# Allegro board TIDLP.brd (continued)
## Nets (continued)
SWNODE_CORE: D502.1 L5.1 Q2.3 U15.25
SWNODE_MOT: D6.1 L6.2 U15.10
SWNODE_MOT2: D3.1 L2.2 U2.10
SWNODE_P2P5V: D7.1 L8.1 U15.41
SWNODE_P3P3V: D8.1 L7.1 U15.43
SWNODE_P5V: D4.1 L4.2 U15.23
TCK: J28.9 J32.15 J47.5 R725.1 U11.N24
TDI: J28.5 J32.19 J47.2 R728.1 U11.N25
TDO1: J47.4 U11.N23
TDO2: J28.13 J32.11 R723.1 U11.N22
TILT_X: R528.2 U3.5
TILT_Y: R529.2 U3.2
TMS1: J47.3 U11.P25
TMS2: J28.7 J32.17 R727.1 U11.P26
TRACECLK: J32.6 RN507.12(B)
TRACECLKR: RN507.5(A) U11.D7
TRACEPKT0: J32.30 J33.1 R659.2 RN508.9(B)
TRACEPKT0R: RN508.8(A) U11.C2
TRACEPKT1: J32.28 J33.2 R658.2 RN508.10(B)
TRACEPKT1R: RN508.7(A) U11.D3
TRACEPKT2: J32.26 J33.3 R657.2 RN508.11(B)
TRACEPKT2R: RN508.6(A) U11.E6
TRACEPKT3: J32.24 J33.4 R656.2 RN508.12(B)
TRACEPKT3R: RN508.5(A) U11.D5
TRACEPKT4: J32.22 J33.5 R655.2 RN508.13(B)
TRACEPKT4R: RN508.4(A) U11.E7
TRACEPKT5: J32.20 J33.6 RN508.14(B)
TRACEPKT5R: RN508.3(A) U11.C4
TRACEPKT6: J32.18 J33.7 RN508.15(B)
TRACEPKT6R: RN508.2(A) U11.B4
TRACEPKT7: J32.16 J33.8 RN508.16(B)
TRACEPKT7R: RN508.1(A) U11.E8
TRACESYNC: J32.32 RN507.13(B)
TRACESYNCR: RN507.4(A) U11.A5
TRSTZ: J32.21 J47.1 R733.1 U11.M23 U516.4
TRSTZ_IN: J28.3 R729.1 R734.2 U516.1
UART0_CTSZ: U6.12 U9.2
UART0_CTSZ_BUF: U9.6 U11.AE2
UART0_CTSZ_CON: J10.7 U6.13
UART0_DCD_CON: J10.1 R12.1
UART0_DSR_CON: J10.6 R12.2 R13.2
UART0_DTR_CON: J10.4 R13.1
UART0_RSTZ_CON: J10.8 U6.14
UART0_RTSZ: U10.5 U11.AD2
UART0_RTSZ_BUF: R542.2 R617.1 U6.11 U10.3
UART0_RXD: R613.1 U6.9 U9.5
UART0_RXD_BUF: U9.3 U11.AD1
UART0_RXD_CON: J10.3 U6.8
UART0_TXD: U10.2 U11.AB3
UART0_TXD_BUF: R543.1 U6.10 U10.6
UART0_TXD_CON: J10.2 U6.7
UART1_CTSZ: U11.E18 U12.12
UART1_CTSZ_CON: J21.7 U12.13
UART1_DCD_CON: J21.1 R21.1
UART1_DSR_CON: J21.6 R21.2 R22.2
UART1_DTR_CON: J21.4 R22.1
UART1_RSTZ_CON: J21.8 U12.14
UART1_RTSZ: U11.A19 U12.11
UART1_RXD: J3.92 U11.D19 U12.9
UART1_RXD_CON: J21.3 U12.8
UART1_TXD: J3.53 U11.C19 U12.10
UART1_TXD_CON: J21.2 U12.7
USB_DAT_N: J5.2 R515.1 U503.4
USB_DAT_NS: DN504.1(TP-1) R515.2 U11.C5
USB_DAT_P: J5.3 R516.1 R539.1 U503.6
USB_DAT_PS: DN504.2(TP-2) R516.2 U11.D6
USB_ENZ: R538.1 U11.E25 U504.1
XCLKIN: R536.1 U7.90
XCLKOUT: TP19.1 U7.66
XTAL_IN: C553.1 R580.1 U11.M26 X500.1
XTAL_OUT: R580.2 R581.2 U11.N26
N16773791: J3.1 R1.2
N16781966: J2.92 R8.2 R9.2
N16826457: Q4.3 R715.2
N16826574: Q3.3 Q4.2 R706.2
N16826732: Q503.3 R726.1
N16826745: Q3.2 R707.2
N16826772: J22.1 R630.2
N16826808: C32.2 Q5.1 R37.1 R726.2
N16827011: C554.1 R581.1 X500.2
N16827097: Q503.2 R599.2
N16827292: R668.1 U15.1
N16827323: R38.2 R52.1 U17.4
N16827429: D9.2 R714.2
N16827460: R39.2 U17.1
N16827499: D9.3 R716.2
N16827743: D10.2 R40.2
N16827874: D9.4 R715.1
N16830133: R684.1 R685.1 U512.1 U512.3 U512.11
N16830205: C667.1 R678.1 R679.2 U15.30 U512.4
N16830232: Q2.2 Q2.4 R634.1 U15.28
N16830236: D5.2 L5.2
N16830344: C675.2 C676.2 Q505.3 R677.2 R680.2 R717.2
N16830356: R639.1 U510.6
N16830372: D5.1 R25.1
N16830397: R640.2 U510.5
N16830529: R637.1 R638.1 U510.1 U510.2 U510.3
N16830564: R682.1 U512.6
N16830576: C675.1 R670.2 R677.1 U15.32 U512.14
N16830606: Q505.1 U15.33
N16830689: R680.1 U512.12
N16830707: R681.2 U512.13
N16830891: R683.2 U512.5
N16836092: C702.2 J64.1 L506.1 R761.1 R779.2
N16836211: R763.2 TP70.1 U521.3 VR2.2
N16862598: J53.3 R785.2 R786.2
N16862628: Q504.2 R687.1
N16862652: R643.2 U511.4
N16862691: R787.2 U526.4
N16862716: C709.2 R774.2 R775.2 U526.5
N16862889: C644.2 R641.2 R642.2 U511.5
N16862891: Q504.3 R686.2
N16869658: J6.1 R530.2 U4.1
N16869662: R548.2 U4.55 U4.56
N16888382: J52.1 J52.8 R753.1
N16888389: J52.13 R737.1
N16888395: J52.11 R739.1
N16888418: J52.12 R738.1
N16902445: J9.5 R626.1 R649.1
N16906032: C21.1 U12.2
N16906053: C20.1 U12.6
N16906057: C577.2 U12.1
N16906061: C577.1 U12.3
N16906093: C576.2 U12.4
N16906098: C576.1 U12.5
N16906262: R540.1 R541.1 U6.16 U9.8 U10.8
N16906499: C8.1 U6.2
N16906505: J5.1 R537.2 U504.2
N16906696: C7.1 U6.6
N16906819: C515.2 U6.1
N16906911: C515.1 U6.3
N16906913: R539.2 U504.4
N16907106: C507.2 U6.4
N16907207: C507.1 U6.5
N16910878: R610.2 U14.53
N16910921: R698.1 R699.2 U14.16
N16911179: R608.2 U14.29
N16911537: R696.2 U14.27
N16912987: R697.2 U14.17
N16969756: R66.2 R506.1 R507.1 R508.2
N16969826: R756.1 U500.1 U520.1
N16973926: C517.2 C518.2 R517.2 U5.5 U5.8
N16985744: R666.1 U2.1
N17028370: R45.1 U517.23
N17028379: R41.1 U517.22
N17028388: R46.1 U517.21
N17028397: R42.1 U517.20
N17028406: R47.1 U517.19
N17028415: R43.1 U517.18
N17028424: R44.1 U517.17
N17028433: R55.1 U517.16
N17028442: R54.1 U517.15
N17028451: R56.1 U517.11
N17031378: C701.2 J65.1 L505.1 R760.1 R778.2
N17031778: C700.2 J66.1 L504.1 R759.1 R777.2
N17032456: C691.2 J42.1 L503.1 R732.1 R744.2
N17032580: C690.2 J43.1 L502.1 R731.1 R743.2
N17032754: C689.2 J44.1 L501.1 R730.1 R742.2
N17036356: R765.2 TP67.1 U521.5 VR1.2
N17038227: J57.2 R768.1
N17038557: J58.2 R782.1
N17038579: R782.2 U522.4
N17059521: R511.1 U501.1 U501.2 U501.3 U501.11
N17059557: C510.1 R523.1 R524.2 U2.30 U501.4
N17059579: Q1.2 Q1.4 R11.1 U2.28
N17059583: D500.2 L1.2
N17059602: D500.1 R525.1
N17059826: R510.2 U501.5
N17060167: R509.1 U501.6
N17126992: R623.2 U11.AC10
N17126998: R624.2 U11.AF10
N17133391: C565.1 FB504.1 J11.1
N17140999: C524.1 R565.2
N17141409: C514.1 FB500.1 U502.4
N17141519: R536.2 U502.3
N17172867: R625.2 U11.AD10
N17173381: C677.2 R709.1 R720.2 TP46.1 U515.3
N17173524: C678.2 R708.1 R709.2
N17223452: C16.1 C521.1 FB4.1 FB5.1 FB6.1 FB7.1 R526.2
N17234365: C15.1 C522.1 FB1.1 FB2.1 FB3.1 R527.2
N17320383: TP25.1 U7.27
N17320387: TP24.1 U7.28
N17320392: TP26.1 U7.29
N17373497: R513.1 R575.1 R588.1
N17385870: R622.2 U11.AB11
N17410797: C529.2 Q500.3 R522.2 R576.2
N17410821: Q500.1 U2.33
N17410829: R521.2 R522.1 U2.32
N17418050: R749.1 U518.12
N17418052: R750.1 U518.9
N17418070: R746.1 U518.7
N17418072: R748.1 U518.4
N17418086: J46.3 U519.22 U525.2
N17418489: J48.1 R747.1 U518.1
N17423586: J46.1 R751.1 U525.4
N17451899: R710.2 SW1.1
N17529082: Q507.2 R776.2
N17529223: Q506.1 Q507.3 R758.1
N17529899: C699.2 J67.1 Q506.3
N17530429: C540.1 Q502.2 R16.1
N17530493: Q501.2 Q502.3 R15.1
N17530807: Q501.3 R573.1
N17554994: R518.1 U501.12
N17554995: R513.2 U501.13
N173644741: C542.2 R574.1

Pads without a net: J5 S1 S2; J9 7 8; J11 6 7; J22 6 7; J29 5 6; J41 5 6; J47 7 8; J49 7 8; J52 15 16; J53 7 8; J54 5 6; J55 5 6; J56 5 6; MT1 2 3 4 5 6 7 8 9; MT2 2 3 4 5 6 7 8 9; MT3 2 3 4 5 6 7 8 9; MT4 2 3 4 5 6 7 8 9; MT5 2 3 4 5 6 7 8 9; MT6 2 3 4 5 6 7 8 9; NOREF#3 1; NOREF#13 1; NOREF#14 1; NOREF#19 1; NOREF#20 1; NOREF#21 1; U20 PAD; U515 5 6 7

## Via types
v1: diameter 0.61, hole 0.305, TOP to BOTTOM, 2108 vias
v2: diameter 0.483, hole 0.229, TOP to BOTTOM, 581 vias

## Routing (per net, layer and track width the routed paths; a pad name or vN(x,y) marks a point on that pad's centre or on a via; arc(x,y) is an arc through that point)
AGND: length 45.6
  TOP w0.203: U7.25 32.88,90.05 33.09,89.83 v1(33.54,89.83)
  TOP w0.254: v1(40.77,91.5) 41.14,91.13 U7.39 ; 34.16,96.02 U7.14 ; 34.16,96.02 34.04,96.14 34.04,96.33 33.85,96.52 U7.13 ; 34.16,96.02 34.42,95.76 34.42,95 v1(34.54,94.87)
  TOP w0.508: J11.2 v1(15.07,95.91) ; v1(20.84,98.25) 20.84,98.76 19.94,99.66 J11.5 15.85,99.66 v1(15.43,100.08)
  BOTTOM w0.254: v1(39.05,90.17) 40.07,89.15 C573.2
  BOTTOM w0.508: R571.2 v1(20.84,98.25) ; C559.2 C560.2 34.37,90.67 v1(33.54,89.83) ; C558.2 34.62,94.79 v1(34.54,94.87) ; C561.2 33.92,95.49 v1(34.54,94.87) ; C574.2 v1(33.34,88.01) ; v1(15.43,100.08) 15.46,100.05 C539.2 R572.2 ; C564.2 20.25,96.22 v1(21.78,97.74) ; C565.2 16.83,95.91 v1(15.07,95.91) ; v1(24.58,94.87) 25.83,94.87 C563.2 ; C575.2 v1(33.46,85.98) ; v1(34.54,94.87) 33.13,93.46 C562.2 ; R583.2 40.83,90.22 40.83,90.11 40.25,89.52 C573.2 40.58,88.82 40.58,88.71 40.64,88.65 R598.2 ; v1(30.61,94.89) 31,95.28 R585.2 ; R586.1 v1(27.11,90.93)
GND: length 1203.6
  TOP w0.178: U11.R5 v2(95.66,67.2) ; U11.F18 v2(85.66,81.2) ; U11.AE17 v2(105.66,80.2) ; U11.B2 v2(81.66,64.2) ; U11.M25 v2(91.66,88.2) ; U11.C3 v2(82.66,65.2) ; U11.F15 v2(85.66,78.2) ; U11.AC6 v2(103.66,68.2) ; U11.A3 v2(80.66,65.2) ; U11.D18 v2(83.66,81.2) ; U11.AC4 v2(103.66,66.2) ; U11.A1 v2(80.66,63.2) ; U11.AB17 v2(102.66,80.2) ; U11.D17 v2(83.66,80.2) ; U11.AB5 v2(102.66,67.2) ; U11.J6 v2(88.66,68.2) ; U11.F21 v2(85.66,84.2) ; U11.AF1 v2(106.66,63.2) ; U11.F6 86.14,68.7 v2(85.66,68.23) ; U11.AD3 v2(104.66,65.2) ; U11.L23 v2(90.66,86.2) ; U11.AF17 v2(106.66,80.2) ; U11.B3 v2(81.66,65.2) ; U11.F9 v2(85.66,71.2) ; U11.R24 v2(95.66,87.2) ; U11.M21 v2(91.66,84.2) ; U11.M22 v2(91.66,85.2) ; U11.AD18 v2(104.66,81.2) ; U11.L25 v2(90.66,88.2) ; U11.P24 v2(94.66,87.2) ; U11.K5 v2(89.66,67.2) ; U11.E15 v2(84.66,78.2) ; U11.G5 v2(86.66,67.2) ; U11.C18 v2(82.66,81.2) ; U11.F12 v2(85.66,74.2) ; U11.A2 v2(80.66,64.2) ; U11.J5 v2(88.66,67.2) ; U11.A24 v2(80.66,87.2) ; U11.B18 v2(81.66,81.2) ; U11.K26 v2(89.66,89.2) ; U11.L5 v2(90.66,67.2) ; U11.V6 v2(98.66,68.2) ; U11.B1 v2(81.66,63.2) ; U11.E17 v2(84.66,80.2) ; U11.AF3 v2(106.66,65.2) ; U11.AE3 v2(105.66,65.2) ; U11.AC17 v2(103.66,80.2) ; U11.AB15 v2(102.66,78.2) ; U11.Y5 v2(100.66,67.2) ; U11.A18 v2(80.66,81.2) ; U11.AA9 v2(101.66,71.2) ; U11.A25 v2(80.66,88.2) ; U11.E16 v2(84.66,79.2) ; U11.B25 v2(81.66,88.2) ; U11.AA12 v2(101.66,74.2) ; U11.E5 v2(84.66,67.2) ; U11.C24 v2(82.66,87.2) ; U11.AB16 v2(102.66,79.2) ; U11.M6 v2(91.66,68.2) ; U11.E22 v2(84.66,85.2) ; U11.D4 v2(83.66,66.2) ; U11.AA6 v2(101.66,68.2) ; U11.W5 v2(99.66,67.2) ; U11.AF2 v2(106.66,64.2) ; U11.U5 v2(97.66,67.2) ; U11.AB14 v2(102.66,77.2) ; U11.AC18 v2(103.66,81.2) ; U11.J21 v2(88.66,84.2) ; U11.R6 v2(95.66,68.2) ; U11.A17 v2(80.66,80.2) ; U11.D23 v2(83.66,86.2) ; U11.B17 v2(81.66,80.2) ; U11.V5 v2(98.66,67.2) ; U11.AD17 v2(104.66,80.2) ; U11.R26 v2(95.66,89.2) ; U11.A26 v2(80.66,89.2) ; U11.N5 v2(92.66,67.2)
  TOP w0.203: U7.69 46.82,99.52 v1(46.72,99.62) ; v1(48.28,57.1) 48.5,57.32 U14.1 ; U7.49 46.14,89.6 v1(45.66,90.08)
  TOP w0.254: U14.33 60,79.64 v1(59.71,79.92) ; U11.AB22 v2(102.66,85.2) ; U8.13 63.92,85.69 63.92,85.68 v1(63.92,85.63) ; U7.62 47.17,96.02 47.07,96.13 v1(47.07,96.26) ; v1(50.17,80.1) 50.49,79.78 U14.52 ; U11.R13 v2(95.66,75.2) ; U11.N15 v2(92.66,78.2) ; v1(183.9,10.46) 184.17,10.74 U20.19 ; U7.89 40.14,102.94 ; 40.14,102.94 40.26,103.06 40.45,103.06 40.64,103.25 U7.88 ; 40.14,102.94 v1(39.94,102.74) ; v1(38.42,84.45) 39.14,85.18 U7.35 ; U15.7 162.18,61.08 v1(161.8,61.47) ; v2(98.66,84.2) U11.V21 ; v1(197.96,14.56) 197.87,14.47 194.21,14.47 J52.9 ; U4.49 78.56,102.37 v1(78.17,101.98) ; U2.19 160.91,115.83 v1(160.53,115.44) ; U11.R14 v2(95.66,77.2) ; U11.M16 v2(91.66,79.2) ; v1(90.17,1.97) 89.65,2.49 J59.5 ; U11.L12 v2(90.66,74.2) ; U11.R15 v2(95.66,78.2) ; v1(46.21,102.56) 46.14,102.63 U7.77 ; U11.P14 v2(94.66,77.2) ; U11.P15 v2(94.66,78.2) ; U11.R11 v2(95.66,73.2) ; U11.P13 v2(94.66,75.2) ; U2.44 161.91,109.97 162.29,110.34 162.29,111.15 v1(161.8,111.63) ; U11.T13 v2(96.66,75.2) ; U11.M13 v2(91.66,75.2) ; v1(59.35,85.89) 59.23,86.01 59.23,86.06 58.69,86.6 U8.12 ; U8.1 57.21,93.74 v1(56.63,94.33) ; U11.N14 v2(92.66,77.2) ; U11.N11 v2(92.66,73.2) ; U11.M14 v2(91.66,77.2) ; U11.AA15 v2(101.66,78.2) ; U2.7 163.45,113.79 v1(163.07,114.17) ; J52.10 196.8,13.94 197.16,13.58 v1(197.16,13.42) ; 159.64,63.25 159.64,63.25 159.64,63.56 159.69,63.61 159.69,64.13 159.64,64.18 U15.19 ; U7.41 42.14,87.48 v1(41.85,87.19) ; U4.8 78.56,108.93 78.18,108.55 78.18,107.62 v1(78.09,107.53) ; U11.P11 v2(94.66,73.2) ; v1(37.34,102.11) 37.34,103.12 37.64,103.43 U7.94 ; J59.11 86.65,2.32 ; U7.2 v1(31.39,102.02) ; U11.N13 v2(92.66,75.2) ; v1(47.08,93.53) 47.16,93.53 47.16,93.49 47.05,93.38 47.08,93.02 47.08,92.8 47.36,92.52 U7.55 ; U14.56 47.86,78.27 47.63,78.5 v1(47.63,78.46) ; U11.N12 v2(92.66,74.2) ; U11.AD24 v2(104.66,87.2) ; U4.19 73.06,111.68 73.04,111.93 72.99,111.97 72.99,112.03 72.99,112.28 v1(72.86,112.4) ; U11.L14 v2(90.66,77.2) ; U7.11 31.73,97.52 v1(31.37,97.16) ; v1(196.04,10.56) 196.16,10.68 196.16,11.28 195.51,11.94 J52.14 ; U11.M12 v2(91.66,74.2) ; U11.AA21 v2(101.66,84.2) ; J59.9 v1(87.65,4.47) ; J59.3 v1(90.65,4.48) ; U11.T15 v2(96.66,78.2) ; J59.7 v1(88.65,2.03) ; U11.AE25 v2(105.66,88.2) ; U11.AF26 v2(106.66,89.2) ; U11.N16 v2(92.66,79.2) ; v1(72.26,100.72) 72.76,101.22 72.76,101.49 72.82,101.56 72.82,102.27 72.83,102.28 72.83,102.37 72.85,102.38 72.85,102.38 73.04,102.58 73.04,102.58 73.06,102.6 U4.38 ; U11.T12 v2(96.66,74.2) ; U11.M15 v2(91.66,78.2) ; U11.P16 v2(94.66,79.2) ; U11.AA18 v2(101.66,81.2) ; U15.44 160.64,57.32 160.67,57.35 160.67,57.35 160.7,57.43 160.75,57.5 160.75,57.53 160.88,57.66 160.88,58.57 v1(160.53,58.93) ; U11.T14 v2(96.66,77.2) ; U11.AE24 v2(105.66,87.2) ; U11.R16 v2(95.66,79.2) ; U7.87 v1(41.14,102.69) ; U11.AC23 v2(103.66,86.2) ; U11.R12 v2(95.66,74.2) ; U11.L13 v2(90.66,75.2) ; U11.AF24 v2(106.66,87.2) ; U11.AF25 v2(106.66,88.2) ; U11.M11 v2(91.66,73.2) ; U11.L15 v2(90.66,78.2) ; U11.P12 v2(94.66,74.2)
  TOP w0.381: J42.3 v1(137.43,23.7) ; C19.2 v1(187.9,89.03) ; J31.3 v1(132.74,35.98) ; RN1.6 v1(42.46,80.54) ; J56.4 v1(52.1,4.67) ; v1(187.39,81.28) 187.85,81.74 C20.2 ; J39.5 v1(14.57,19.08) ; J60.3 v1(99.72,4.97) ; J30.3 119.54,37.67 119.18,37.32 v1(118.98,37.32) ; J57.3 63.77,3.38 v1(63.44,3.05) ; J33.10 v1(60.71,41.91) ; v1(172.66,22.42) 173.52,23.28 U16.4 ; U13.34 v1(33.45,67.55) ; D3.2 v1(167.04,103.91) ; D9.1 174.29,42.43 v1(174.22,42.5) ; U5.2 186.5,107.44 v1(187.26,106.68) ; U3.7 v1(178.12,113.79) ; J32.G5 48.26,39.37 J32.5 ; C29.1 v1(188.39,35.97) ; C17.1 v1(137.03,100.9) ; v1(73.47,3.17) 73.68,3.38 J58.3 ; v1(178.31,105.21) 178.55,104.97 C18.2 ; RN1.8 v1(44.18,80.5) 44.16,80.52 43.48,80.52 43.26,80.74 RN1.7 ; J38.1 2.9,14.08 2.67,13.84 2.67,13.08 v1(2.41,12.83) ; RN1.5 v1(41.55,79.72) ; R52.2 v1(180.85,28.26) ; U9.4 v1(128.85,85.93) ; C8.2 v1(191.13,116.14) ; U5.3 v1(184.86,110.1) ; R5.2 v1(168.47,119.32) ; U10.4 v1(133.24,85.93) ; J33.9 v1(57.53,39.37) ; U12.15 v1(191.74,68.54) ; v1(42.61,67.92) 43.03,68.34 U13.12 ; J54.4 v1(26.29,3.17) ; U3.3 v1(186.75,116.33) ; J10.5 v1(194.9,100.76) ; C7.2 v1(188.72,115.95) ; v1(178.57,25.96) 178.56,25.95 178.56,25.15 179.13,24.58 U16.7 ; U6.15 191.36,104.18 v1(191.83,104.65) ; J41.4 125.76,25.82 v1(125.79,25.85) ; v1(162.69,23.04) 162.76,23.11 163.7,23.11 163.85,23.26 J44.3 ; C21.2 v1(193.22,81.74) ; C28.1 184.25,35.97 v1(183.9,36.32) ; J24.1 v1(16.07,58.42) ; D10.1 v1(184.83,28.85) ; C37.1 v1(190.3,9.09) ; J55.4 v1(40.03,4.6) ; J47.6 v1(31.17,12.75) ; C33.1 v1(179.32,28.07) ; J33.11 v1(57.66,44.45) ; J49.6 v1(45.77,12.59) ; C1.1 166.12,124.08 166.75,123.44 v1(166.75,122.3) ; C26.1 v1(192.66,66.23) ; U19.2 v1(173.8,20.19) ; J22.5 v1(181.42,57.36) ; J24.20 v1(26.99,35.56) ; J33.12 v1(60.71,46.99) ; J67.3 174.01,2.2 v1(174.4,1.82) ; U18.3 v1(127.62,20.02) ; J21.5 v1(194.99,68.25) ; J53.2 v1(17.12,1.43)
  TOP w0.508: J5.4 7.83,104.47 v1(10.83,104.47) ; v1(88.44,109.1) 88.44,109.17 88.75,109.48 C14.2 ; Q4.1 175.14,46.23 v1(174.32,46.23) ; v1(152.92,47.76) 152.92,48.65 D8.2 ; D6.2 v1(169.56,51.21) ; v1(138.87,2.29) 138.87,2.33 139.72,3.17 J64.3 ; v1(73.91,116.97) 73.89,116.99 J2.G8 69.95,116.99 v1(69.91,117.03) 69.88,116.99 J2.G7 63.6,116.99 v1(63.56,117.03) 63.53,116.99 J2.G6 57.24,116.99 v1(57.21,116.97) 57.19,116.99 J2.G5 J2.G4 49.87,116.99 v1(49.85,116.97) 49.82,116.99 J2.G3 43.52,116.99 v1(43.5,116.97) 43.47,116.99 J2.G2 37.3,116.99 v1(37.27,116.97) 37.25,116.99 J2.G1 33.36,116.99 v1(33.34,116.97) ; v1(108.19,39.74) 107.98,39.53 J29.4 ; J43.3 150.87,23.7 v1(150.54,23.37) ; C13.2 87.48,109.12 v1(87.46,109.12) ; C23.1 v1(152.02,67.82) ; v1(163.97,73.78) 163.97,73.18 164.85,72.31 C22.1 ; D1.2 v1(135.47,112.5) ; C10.2 38.1,109.82 39.04,108.87 v1(40.01,108.87) ; VR1.1 v1(94.86,12.81) ; v1(84.38,116.6) 84.77,116.99 J3.G1 88.3,116.99 v1(88.33,116.97) 88.35,116.99 J3.G2 94.39,116.99 94.44,117.04 95.4,117.04 95.43,117.02 95.56,117.02 95.59,116.99 J3.G3 100.94,116.99 v1(100.97,116.97) 101.2,116.97 101.38,116.79 102.22,116.79 102.42,116.99 J3.G4 J3.G5 108.31,116.99 108.33,116.97 108.36,116.99 J3.G6 114.66,116.99 v1(114.68,116.97) 114.71,116.99 J3.G7 120.94,116.99 v1(120.97,116.97) 120.99,116.99 J3.G8 124.87,116.99 v1(125.01,117.13) ; v1(143.38,45.59) 142.65,46.33 D7.2 ; v1(85.92,1.91) 86.23,1.91 86.65,2.32 ; v1(162.5,2.16) 163.22,2.88 J66.3 ; C36.1 115.18,13.2 113.92,11.94 109.7,11.94 109.58,12.06 108.39,12.06 107.95,12.51 107.95,14.52 v1(108.27,14.83) 108.42,14.99 C35.1 ; C3.2 v1(38.73,124.52) ; R23.2 v1(166.69,69.67) ; J65.3 151.79,3.26 v1(150.81,2.29) ; D2.2 152.59,105.41 v1(151.01,106.99) ; v1(168.96,49.08) 169.92,49.08 Q3.1 ; J62.3 119.4,4.87 v1(119.13,5.15) ; v1(82.09,33.62) 81.94,33.77 C31.1 ; J35.3 v1(136.23,32.45) ; C9.2 v1(35.67,109.97) ; C11.2 v1(40.19,109.97) ; v1(94.62,34.98) 94.62,35.05 94.74,35.05 94.74,35.05 95.49,34.3 R34.2 ; C25.1 v1(167.06,66.56) ; C12.2 v1(86.21,109.13) ; C5.2 90.66,124.16 v1(91.03,124.52) 90.21,125.34 89.52,125.34 88.77,124.59 C4.2 ; C27.1 v1(135.57,48.56) ; v1(43.5,108.33) 42.48,107.31 J7.2 ; J9.6 v1(61.86,105.54) ; VR2.1 v1(122.14,15.39) ; C30.1 v1(78.35,34.81) ; C34.1 v1(26.37,26.99) ; C2.2 v1(37.47,124.52)
  LY2GND w0.508: TP44.1 163.52,54.36 162.79,53.63 ; TP44.1 164.34,53.21 164.37,53.17 ; TP44.1 166.55,54.36 166.81,54.1 ; TP44.1 164.34,55.51 164.55,55.72 ; J23.16 7.01,43.27 ; J23.16 5.5,43.27 ; J23.16 5.5,41.76 ; J23.16 7.01,41.76 ; J48.2 50.44,21.13 ; J48.2 48.81,19.51 ; J48.2 50.44,19.51 ; J48.2 48.81,21.13 ; 48.81,50.98 J25.2 ; J25.2 48.81,49.35 ; J25.2 50.44,50.98 ; J25.2 50.44,49.35 ; 83.86,14.78 J50.2 ; J50.2 85.49,14.78 ; J50.2 83.86,13.16 ; J50.2 85.49,13.16 ; 18.93,115.45 19.68,116.2 ; 19.68,116.2 18.93,116.96 ; 19.68,116.2 20.44,116.96 ; 19.68,116.2 20.44,115.45 ; J40.14 22.92,13.54 24.27,13.54 ; J40.14 22.86,12.46 22.82,12.42 ; J40.14 J40.13 ; J40.14 21.1,13.6 21.09,13.59 ; J28.16 35.1,45.26 ; J28.16 35.1,43.64 ; J28.16 33.48,45.26 ; J28.16 33.48,43.64 ; 66.18,97.71 J17.2 ; J17.2 67.81,97.71 ; J17.2 65.87,98.52 65.85,98.5 ; J17.2 66.99,98.88 66.23,99.64 ; J17.2 67.81,99.33 ; J17.2 66.18,99.33 ; J17.2 68.45,98.52 68.47,98.5 ; 185.27,5.23 186.06,4.45 ; 186.06,4.45 186.84,5.23 ; 186.06,4.45 186.84,3.66 ; 186.06,4.45 185.27,3.66 ; 48.17,40.73 J32.G5 ; J32.G5 49.62,39.28 ; J32.G5 48.17,39.28 ; J32.G5 49.62,40.73 ; J32.G1 49.62,30.57 ; J32.G1 49.62,29.12 ; J32.G1 48.17,29.12 ; J32.G1 48.17,30.57 ; U1.2 13.49,119.86 ; U1.2 11.91,119.86 ; U1.2 11.91,121.44 ; U1.2 13.49,121.44 ; J28.6 35.1,30.94 ; J28.6 33.48,32.56 ; J28.6 33.48,30.94 ; J28.6 35.1,32.56 ; 33.48,48.72 J28.20 ; J28.20 35.1,48.72 ; J28.20 35.1,50.34 ; J28.20 33.48,50.34 ; 8.26,42.52 9.01,43.27 ; 8.26,42.52 7.5,41.76 ; 8.26,42.52 7.5,43.27 ; 8.26,42.52 9.01,41.76 ; 18.93,110.37 19.68,111.12 ; 19.68,111.12 18.93,111.88 ; 19.68,111.12 20.44,110.37 ; 19.68,111.12 20.44,111.88 ; J6.2 38.06,108.13 ; J6.2 38.06,106.5 ; J6.2 36.43,108.13 ; J6.2 36.43,106.5 ; J23.10 7.01,47.76 ; J23.10 7.01,49.27 ; J23.10 5.5,49.27 ; J23.10 5.5,47.76 ; 6.56,74.91 J20.5 ; J20.5 6.56,73.19 ; J20.5 8.28,73.19 ; J20.5 8.28,74.91 ; J37.3 191.9,31.26 ; J37.3 190.37,31.26 ; J37.3 191.9,32.8 ; J37.3 190.37,32.8 ; J5.4 6.99,106.78 ; J5.4 5.52,106.78 ; J5.4 5.52,105.31 ; J5.4 6.99,105.31 ; 185.42,12.69 185.47,12.73 ; 185.42,12.69 U20.25 ; 185.42,12.69 185.35,12.61 ; J32.G2 49.62,33.11 ; J32.G2 48.17,33.11 ; J32.G2 48.17,31.66 ; J32.G2 49.62,31.66 ; 20.87,14.88 22.82,14.88 J40.13 ; 48.17,38.19 J32.G4 ; J32.G4 48.17,36.74 ; J32.G4 49.62,36.74 ; J32.G4 49.62,38.19 ; J37.1 191.9,25.27 ; J37.1 190.37,25.27 ; J37.1 190.37,26.8 ; J37.1 191.9,26.8 ; J40.13 22.9,14.81 24.24,14.81 ; 48.17,35.65 J32.G3 ; J32.G3 49.62,34.2 ; J32.G3 48.17,34.2 ; J32.G3 49.62,35.65 ; J37.5 194.9,25.27 ; J37.5 193.36,26.8 ; J37.5 194.9,26.8 ; J37.5 193.36,25.27 ; 7.5,49.76 J23.7 ; J23.7 9.01,49.76 ; J23.7 9.01,51.27 ; J23.7 7.5,51.27 ; J28.8 35.1,33.48 ; J28.8 33.48,35.1 ; J28.8 35.1,35.1 ; J28.8 33.48,33.48 ; 33.48,37.64 J28.10 ; J28.10 33.48,36.02 ; J28.10 35.1,36.02 ; J28.10 35.1,37.64 ; 19.68,118.75 20.44,117.99 ; 19.68,118.75 20.44,119.5 ; 19.68,118.75 18.93,119.5 ; 19.68,118.75 18.93,117.99 ; 190.89,3.51 190.9,3.5 MT6.1 196.5,9.15 196.33,9.32 ; 18.93,122.04 19.68,121.28 ; 19.68,121.28 20.44,122.04 ; 19.68,121.28 20.44,120.53 ; 19.68,121.28 18.93,120.53 ; J28.18 35.1,46.18 ; J28.18 35.1,47.8 ; J28.18 33.48,46.18 ; J28.18 33.48,47.8 ; U20.25 186.59,13.65 186.63,13.61 ; U20.25 185.42,14.67 185.46,14.71 ; U20.25 184.35,13.65 184.31,13.69 ; 188.25,127.58 188.34,127.5 MT3.1 196.5,122.45 196.1,122.05 ; 3.52,9.4 3.5,9.38 MT5.1 8.57,3.5 8.65,3.58 ; 193.36,31.26 J37.7 ; J37.7 194.9,32.8 ; J37.7 194.9,31.26 ; J37.7 193.36,32.8 ; 33.48,38.56 J28.12 ; J28.12 35.1,38.56 ; J28.12 35.1,40.18 ; J28.12 33.48,40.18 ; J28.4 35.1,30.02 ; J28.4 33.48,28.4 ; J28.4 35.1,28.4 ; J28.4 33.48,30.02 ; J28.14 35.1,41.1 ; J28.14 33.48,41.1 ; J28.14 35.1,42.72 ; J28.14 33.48,42.72
  LY2GND w1.27: 138.34,129.51 138.32,129.5 MT2.1 ; 3.45,125.04 3.45,120.05 MT4.1 ; MT2.1 127.57,129.5 127.45,129.37 ; MT2.1 132.63,124.76 132.5,124.64 ; MT1.1 25.63,124.27 25.48,124.12 ; MT1.1 25.59,129.53 19.63,129.53 ; MT1.1 30.94,129.5 31.07,129.63 ; MT4.1 3.35,119.85 3.35,115.77 ; MT4.1 3.51,120.01 8.06,120.01
  BOTTOM w0.102: C548.2 86.69,90.81 86.66,90.83 ; C549.2 96.32,90.42 95.66,89.76 v2(95.66,89.2) ; C602.2 88.76,81.41 ; C550.2 84.4,90.83 ; v2(90.66,86.2) 91.06,85.8 93.4,85.8 C546.2 ; v2(89.48,72.05) 89.57,72.05 89.53,72.01 v2(89.53,70.99) ; C645.2 93.83,88.69 92.15,88.69 v2(91.66,88.2) ; v2(89.66,89.2) 88.95,89.91 C547.2
  BOTTOM w0.254: v1(160.53,62.74) 160.22,63.04 C640.2 ; U512.2 139.59,56.1 139.84,55.86 139.84,55.08 139.39,54.63 138.5,54.63 138.41,54.74 v1(138.05,54.74) ; v2(91.66,73.2) 91.64,73.18 C625.2 ; v2(92.62,81.38) 92.67,81.43 C596.2 ; v1(176.21,116.2) 175.59,115.59 U501.10 ; v2(95.66,73.2) 95.68,73.18 C620.2 ; v1(163.07,114.17) 163.4,113.84 C512.1 ; C632.2 87.74,69.22 C628.2 88.6,70.05 v2(89.53,70.99) ; U512.10 142.76,58.05 142.03,58.78 142.03,59.76 141.35,60.44 140.4,60.44 139.95,59.99 v1(139.66,59.99) ; v1(90.65,4.48) 90.54,4.37 C705.1 ; v2(88.39,71.31) 88.33,71.25 C630.2 C631.2 ; U517.1 v1(31.73,27.6) ; U510.11 142.04,62.99 v1(141.44,62.38) ; v1(161.8,61.47) 162.13,61.14 C639.1 ; v1(177.26,112.82) 176.89,113.18 U501.8 ; v2(93.66,82.02) 93.79,82.14 C569.2 ; v2(90.81,70.99) C626.2 90.74,69.99 C627.2 ; U507.3 23.7,76.39 ; C595.2 95.19,82.35 94.93,82.09 94.93,81.66 v2(94.81,81.53) ; C594.2 96.11,82.26 96.11,81.95 95.69,81.53 v2(95.72,81.53) ; C568.2 99.87,82.61 C586.2 99.81,81.6 C590.2 99.69,81.53 v2(99.06,80.9) ; U517.12 v1(31.73,18.11) ; v1(145.45,60.33) 144.91,60.33 144.08,59.5 U512.8 ; C629.2 87.99,73.41 88.11,73.29 88.55,73.29 88.61,73.34 v2(89.09,73.34) ; U510.8 144.61,64.94 144.88,65.22 145.87,65.22 146.01,65.07 v1(146.01,65.06) ; v2(91.17,81.38) 91,81.56 C597.2 ; C622.2 94.61,70.93 v2(94.6,70.94) ; v2(88.81,81.36) 87.74,82.42 C601.2 C570.2 ; C606.1 54.99,75.69 54.94,75.64 54.94,75.68 54.91,75.68 54.91,75.68 54.91,75.68 54.91,75.68 54.91,75.68 v1(54.9,75.68) ; v2(88.68,80.09) 88.73,80.14 C598.2 ; v1(142.3,63.64) 142.31,63.64 142.31,63.64 U510.10 ; C588.2 v2(98.68,78.74) ; C624.2 v2(92.39,70.99) ; C600.2 89.79,82.28 C599.2 89.85,81.41 v2(89.9,81.36) ; C618.2 98.11,70.92 v2(98.13,70.94) ; C619.2 v2(96.71,70.92) ; v2(98.11,81.22) 98.74,81.85 C591.2 ; v2(88.39,72.52) 88.27,72.39 C633.2 ; R755.2 v1(188.34,11.43) ; U517.13 24.82,18.9 v1(24.25,19.47) ; U509.3 v1(24.13,71.63)
  BOTTOM w0.381: RN501.5 42.02,99.02 41.82,99.21 41.82,99.92 v1(41.83,99.93) RN501.6 ; U506.5 28.74,84.8 v1(29.03,85.09) 28.68,85.45 U506.4 ; C611.2 113.78,70.1 113.95,69.93 v1(114.64,69.93) ; C543.2 v1(179.39,92.08) ; C706.1 v1(63.44,3.05) ; C536.2 31.75,102.37 v1(31.39,102.02) ; R769.1 v1(59.82,8.51) ; DN501.1 v1(168.17,130.33) ; v2(98.87,72.39) 99.62,72.39 C615.2 ; R757.2 183.51,12.18 183.88,11.81 183.88,11.81 C693.1 184.26,10.77 183.9,10.4 v1(183.9,10.46) ; U506.1 v1(29.65,87.39) ; C659.2 95,66.54 v2(95.66,67.2) ; U521.4 108.19,6.14 108.1,6.05 v1(108.1,6.14) ; C682.1 v1(139.76,37.59) ; R574.2 174.24,95 v1(173.93,94.68) ; v1(178.63,106.49) 178.88,106.24 179.77,106.24 180.26,105.74 C518.1 ; v2(101.66,68.2) 101.66,68.4 C614.2 ; v1(46.21,102.56) 45.35,103.42 C531.2 ; R734.1 37.66,25.08 37.66,25.14 v1(37.69,25.14) ; v2(110.82,67.54) 110.59,67.31 R650.1 C652.2 ; C695.1 103.38,11.05 v1(103.06,11.37) ; v1(19.18,6.35) 19.56,6.73 C698.1 ; C604.2 88.28,78.87 v2(88.48,79.07) ; U524.3 v1(15.19,6.78) ; C707.1 61.91,4.19 v1(61.53,3.81) ; U516.2 v1(40.26,26.04) ; v1(33.45,67.55) 33.32,67.42 C662.1 ; v1(75.31,9.21) 75.11,9 U522.3 ; C651.2 114.08,60.71 v1(114.47,61.1) 114.1,61.47 C650.2 ; C704.1 v1(98.3,3.17) ; C653.2 110.81,63.75 v2(110.87,63.7) ; C664.2 186.13,54.08 186.35,53.85 v1(186.35,52.5) ; C517.1 181.36,107 v1(182.12,107.76) ; v1(47.07,96.26) 47.08,96.25 C556.2 ; C544.2 174.5,96.01 v1(174.05,96.46) ; v1(189.18,94.25) 189.18,94.25 189.19,94.25 189.19,94.24 189.55,94.59 189.78,94.59 190.26,95.07 Q501.1 ; C534.2 37.34,103.62 v1(37.34,102.11) ; C535.2 v1(31.94,104.27) ; v1(57.18,54.33) 57.18,54.62 57.2,54.62 57.18,54.63 R698.2 ; C679.1 v1(43.07,51.8) ; C656.2 106.66,62.34 v2(106.66,63.2) ; U503.5 12.57,113.36 12.86,113.64 13.86,113.64 14.38,114.17 v1(14.73,114.17) ; R569.2 43.18,105.41 v1(43.56,105.79) ; v1(42.79,46.74) 42.79,45.94 42.73,45.88 42.13,45.88 U513.3 ; C621.2 v2(95.69,71.05) ; v1(14.16,7.3) 13.53,7.3 13.26,7.57 U526.3 ; U516.3 v1(40.31,26.97) ; C697.1 72.26,8.19 v1(71.63,8.83) ; Q507.1 171.53,4.78 170.81,4.06 v1(170.81,3.3) ; C709.1 v1(9.26,3.95) ; R773.1 21.46,6.73 v1(22.73,5.46) ; v1(40.51,43.56) 40.78,43.83 U513.1 ; v1(130.65,84.57) 130.65,84.61 130.54,84.72 C567.1 ; C654.2 110.45,62.23 110.85,61.84 110.85,61.75 110.99,61.6 v2(110.85,61.6) ; U523.3 v1(61.52,8.62) ; C527.1 v1(191.39,98.81) ; C696.1 v1(93.09,8.95) ; v1(17.12,1.43) 17.14,1.46 C708.1 ; C637.1 v1(187.78,66.88) ; U520.3 v1(184.96,6.55) ; C638.2 v1(189.29,62.87) ; C613.2 99.81,71.06 C616.2 99.29,71.12 98.9,71.52 v2(98.9,71.48) ; C649.2 v1(114.42,63.75) ; v1(177.61,127.44) 177.14,126.97 DN500.1 ; U523.1 v1(60.27,5.66) ; C681.1 v1(140.04,42.39) ; C516.1 186.89,107.05 v1(187.26,106.68) ; R703.2 v1(53.06,51.66) ; Q502.1 v1(190.32,90.12) ; C605.2 86.21,78.2 v2(85.66,78.2) ; C537.2 31.48,97.27 v1(31.37,97.16) ; C663.1 42.66,67.87 v1(42.61,67.92) ; U506.2 28.71,86.75 v1(28.97,86.49) 28.58,86.1 U506.3 ; U519.12 v1(5.82,18.05) ; C646.2 v1(114.56,68.45) ; C603.2 88.63,80.14 v2(88.68,80.09) ; C694.1 120.65,5.79 121.28,5.15 v1(121.28,4.95) ; U514.1 v1(44.4,50.5) ; C699.1 v1(174.4,1.82) ; v1(42.54,19.3) 42.54,17.66 42.81,17.39 C692.1 ; C525.2 v1(29.02,104.78) ; v1(189.33,104.82) 189.33,104.62 189.1,104.39 R542.1 ; C618.2 98.23,70.12 C617.2 ; v1(134.75,39.75) 135.13,39.37 C683.1 ; U518.15 v1(47.35,17.5) ; v1(51.63,12.55) 51.86,12.77 U518.8 ; v1(72.86,112.4) 72.89,112.38 C523.1 ; C541.1 v1(182.27,91.91) ; C688.1 173.81,20.21 v1(173.8,20.19) ; C687.1 172.72,22.48 v1(172.66,22.42) ; C648.2 113.88,65.28 v1(114.64,66.04) C647.2 ; D501.1 v1(173.84,102.59) ; v2(81.66,63.2) 81.58,63.12 C661.2 ; U508.14 v1(184.01,74.72) ; U519.13 v1(10.07,18.84) ; v1(3.73,9.91) 4.15,10.33 U519.1 ; v1(181.3,42.68) 181.3,43.64 181.79,44.14 C672.2 ; C579.1 v1(183.01,81.66) ; C508.1 C509.1 179.72,113.36 v1(179.13,112.78) ; C524.2 v1(50.36,104.65) ; v1(122.75,39.83) 122.75,39.8 122.03,39.08 C684.1 ; C677.1 131.27,45.8 v1(131.7,46.23) ; C623.2 v2(93.54,72.32) ; U505.7 v1(181.04,97.28) ; RN501.8 v1(41.83,101.64) 41.82,101.64 41.82,100.94 42.03,100.73 RN501.7 ; v1(18.8,8) 18.41,7.62 18.41,7.49 18.08,7.16 U524.1 ; C540.2 v1(194.01,95.33) ; U526.1 v1(11.38,9.19) ; C607.1 v1(193.04,74.8) ; C578.2 v1(181.67,76.58) ; C678.1 124.14,44.7 v1(124.12,44.73) ; U506.13 v1(22.85,80.25) ; C634.2 86.22,74.21 86.06,74.21 86.05,74.2 v2(85.66,74.2) ; U522.1 v1(73.23,9.07) ; C566.2 v1(179.45,88.9) ; C538.2 v1(22.35,99.69) ; C685.1 v1(42.67,42.55) ; R600.1 v1(185.53,81.42) ; Q503.1 v1(177.91,80) ; U515.4 v1(132.76,42.63) ; RN503.5 v1(41.83,92.67) ; U514.2 v1(43.12,48.58)
  BOTTOM w0.483: v1(78.13,20.32) J500.25A ; v1(87.02,27.94) J500.18F ; C519.1 161.8,106.22 161.8,105.16 v1(162.31,104.65) ; v1(88.29,25.4) J500.17D ; v1(92.1,27.94) J500.14F ; v1(85.75,20.32) J500.19A ; v1(109.88,25.4) J500.1D ; J500.11A v1(97.18,20.32) ; v1(85.75,25.4) J500.19D ; v1(104.8,20.32) J500.5A ; v1(100.99,22.86) 100.36,23.5 ; 79.74,23.2 v1(79.4,22.86) ; v1(103.53,22.86) 102.9,23.5 ; v1(102.26,20.32) J500.7A ; v1(83.21,20.32) J500.21A ; v1(80.67,25.4) J500.23D ; v1(80.67,20.32) J500.23A ; v1(88.29,20.32) J500.17A ; v1(106.07,22.86) 105.44,23.5 ; v1(108.61,22.86) 107.98,23.5 ; 95.28,23.5 v1(95.91,22.86) ; v1(83.21,25.4) J500.21D ; v1(109.88,20.32) J500.1A ; v1(81.94,27.94) J500.22F ; v1(79.4,27.94) J500.24F ; v1(78.13,25.4) J500.25D ; v1(89.56,27.94) J500.16F ; v1(84.48,27.94) J500.20F ; v1(99.72,20.32) J500.9A ; v1(81.94,22.86) 82.03,22.95 ; 97.82,23.5 v1(98.45,22.86) ; v1(92.1,24.13) J500.14C ; v1(107.34,20.32) J500.3A ; v1(90.83,25.4) J500.15D ; v1(90.83,20.32) J500.15A
  BOTTOM w0.508: R788.1 25.29,72.44 24.48,71.63 v1(24.13,71.63) ; RN502.5 55.1,90.76 v1(54.71,91.15) 55.23,91.68 RN502.6 ; v1(82.04,91.31) 83.92,91.31 84.4,90.83 ; R791.1 72.93,85.09 v1(72.9,85.12) ; RN500.8 54.85,108.54 v1(54.85,108.54) ; C666.1 156.8,52.17 v1(156.8,51.86) ; 23.4,131.72 MT1.1 ; C551.1 v1(106.55,98.77) ; C521.2 v1(100.6,94.18) 102.11,92.67 C16.2 ; R670.1 v1(154.14,53.1) ; v1(157.99,58.93) 157.61,58.55 156.91,58.55 156.9,58.53 R669.2 ; C572.2 41.9,87.24 v1(41.85,87.19) 41.77,87.11 R598.1 ; v1(25.2,75.7) R790.1 23.7,76.39 ; v1(95,92.84) 94.87,92.96 C554.2 ; v1(161.8,115.44) 161.49,115.75 C513.2 ; U504.3 14.66,108.22 v1(15.3,107.57) ; C643.1 130.31,62.26 v1(130.14,62.08) ; DN507.1 v1(153.87,80.8) ; C660.2 v1(94.17,60.19) ; C555.2 73.27,92.08 v1(71.82,92.08) ; C506.1 8.32,123.05 8.32,121.92 v1(8.19,121.79) ; C529.1 v1(153.1,97.28) ; C526.1 v1(14.11,103.96) ; C533.2 39.76,102.92 v1(39.94,102.74) ; C610.2 v1(123.48,69.34) ; v1(41.14,102.69) 41.14,102.69 C532.2 ; v1(85.15,93.04) 85.15,92.34 86.66,90.83 ; v1(56.63,94.33) 56.45,94.15 56.23,94.15 56.03,93.95 RN502.8 55.46,93.39 55.2,93.13 55.2,92.7 55.43,92.47 RN502.7 ; R664.1 v1(23.88,66.99) ; v1(112.39,1.27) 111.66,2.01 C703.1 ; R792.1 v1(72.2,90.55) ; U503.2 v1(12.57,116.14) ; U506.12 26.27,80.25 v1(25.92,80.59) 26.22,80.89 U506.11 ; RN504.8 55.89,89.12 55.31,89.12 v1(55.01,88.81) 55.45,88.37 56.01,88.37 RN504.7 ; C511.1 v1(169.81,116.26) ; v1(54.85,109.46) RN500.7 ; J500.2F v1(108.61,27.94) ; C552.2 v1(104.14,95.75) ; C670.2 v1(85.41,57.47) ; C522.2 v1(80.99,96.67) ; 130.4,131.72 MT2.1 ; R520.2 v1(167.26,109.61) ; v1(149.08,58.91) 148.2,58.03 R679.1 147.6,57.06 147.6,56.33 147.51,56.24 147.51,56.11 147.28,55.88 R681.1 ; R524.1 149.47,110.77 v1(150,111.3) ; C673.1 v1(164.27,49.72) ; C676.1 v1(151.78,44.58) ; C657.2 v1(100.25,60.19) ; J500.9D v1(99.72,25.4) ; J500.20C v1(84.48,22.86) ; R537.1 v1(15.47,109.09) ; R710.1 v1(69.14,13.51) ; 194.27,1.27 MT6.1 ; v1(120.56,56.88) 120.4,57.04 R688.2 ; C680.1 v1(152.78,42.9) ; DN503.1 158.36,128.96 158.14,128.73 v1(157.53,128.73) ; R518.2 174.45,110.01 175.18,110.74 175.58,110.74 v1(175.58,110.74) ; RN500.6 54.62,110.25 v1(54.85,110.49) ; U502.2 v1(42.42,110.93) ; U500.3 v1(14.3,121.98) ; C15.2 78.56,93.22 v1(76.4,95.38) ; C669.2 v1(91.76,59.11) ; C665.1 160.65,53.4 v1(160.65,52.1) ; v1(12.77,12.86) 13.05,13.14 U525.3 ; DN506.1 159.36,85.46 158.55,84.65 v1(158.53,84.65) ; Q504.1 125.72,55.32 125.72,55.07 v1(125.97,55.07) ; R705.2 48.94,57.81 48.28,57.14 v1(48.28,57.1) ; DN502.1 161.56,126.59 160.98,127.17 v1(160.41,127.17) ; C530.2 46.81,99.71 v1(46.72,99.62) ; v1(72.49,88.14) 72.59,88.03 72.6,88.03 72.6,88.04 72.75,87.88 R789.1 ; C514.2 v1(34.47,113.03) ; R597.2 78.47,96.61 v1(77.47,96.61) ; C608.2 v1(134.51,74.5) ; J500.8F v1(100.99,27.94) ; RN504.6 55.35,87.55 v1(54.8,87) 55.17,86.63 RN504.5 ; R793.1 v1(18.54,72.64) ; J500.13D v1(94.64,25.4) ; C686.1 v1(17.03,28.24) ; 82.03,22.95 82.07,22.95 82.58,23.46 J500.22C ; C644.1 125.54,66.41 126.02,66.89 v1(126.02,66.94) ; C584.2 v1(99.43,91.71) ; C668.2 v1(130.62,51.36) ; J500.12F v1(95.91,27.94) ; C553.2 88.44,92.96 v1(88.23,93.17) ; v1(47.08,93.53) 47.16,93.53 47.16,93.28 47.61,92.82 C557.2 ; C571.2 45.99,89.6 45.66,89.93 v1(45.66,90.08) ; J500.4F v1(106.07,27.94) ; J500.6F v1(103.53,27.94) ; J500.11D v1(97.18,25.4) ; R510.1 v1(176.61,123.08) ; v2(95.31,80.39) 95.69,80.77 C593.2 ; C503.1 v1(16.26,129.1) ; RN500.5 54.46,111.17 54.8,111.51 v1(54.85,111.51) ; J500.18C v1(87.02,22.86) ; U511.1 v1(124.45,61.01) ; J500.7D v1(102.26,25.4) ; R640.1 v1(130.18,64.54) ; 5.73,1.27 MT5.1 ; R683.1 132.63,58.67 v1(131.82,59.48) ; C671.2 77.19,58.34 v1(76.8,58.73) ; R585.1 v1(29.96,96.85) ; DN505.1 162.03,84.87 161.83,84.68 161.83,84.43 v1(161.81,84.43) ; C504.1 v1(14.1,129.1) ; C658.2 v1(97.46,60.19) ; U511.3 v1(120.38,61.01) ; J500.3D v1(107.34,25.4) ; J500.10F v1(98.45,27.94) ; 198.73,125.27 MT3.1 ; 132.72,69.72 v1(134.8,69.72) ; J500.16C v1(89.56,22.86) ; R521.1 v1(154.18,106.95) ; U1.2 v1(12.7,122) ; DN508.1 v1(164.92,69.9) ; C520.1 v1(159.07,105.91) ; C545.1 v1(152.39,93.22) ; R571.1 v1(19.8,98.25) ; J500.24C 79.74,23.2 ; C636.1 v1(20.31,70.69) ; C635.1 v1(20.31,75.77) ; J500.5D v1(104.8,25.4) ; J8.3 v1(51.75,107.31) ; C655.2 C654.2
  BOTTOM w0.635: D507.2 148.36,3.71 v1(147.27,3.71) ; v1(169.5,2.21) 169.5,3.72 C700.1 ; C701.1 v1(158.62,4.06) ; v1(158.99,17.47) 159.3,17.78 D503.2 ; C690.1 158,18.03 v1(158.75,18.79) ; D506.2 v1(160.53,2.66) ; D504.2 v1(146.94,17.78) ; D508.2 v1(134.87,3.81) ; C702.1 145.36,4.39 v1(146.38,4.39) ; C691.1 v1(145.29,18.03) ; C689.1 v1(170.69,18.03) ; D505.2 v1(133.6,17.78)
  vias: v1(1.27,131.72) v1(1.27,129.18) v1(1.27,126.64) v1(1.27,124.1) v1(1.27,113.94) v1(1.27,111.4) v1(1.27,108.86) v1(1.27,106.32) v1(1.27,103.78) v1(1.27,101.24) v1(1.27,98.7) v1(1.27,96.16) v1(1.27,93.62) v1(1.27,86) v1(1.27,83.46) v1(1.27,80.92) v1(1.27,78.38) v1(1.27,75.84) v1(1.27,73.3) v1(1.27,70.76) v1(1.27,63.14) v1(1.27,60.6) v1(1.27,58.06) v1(1.27,55.52) v1(1.27,52.98) v1(1.27,50.44) v1(1.27,47.9) v1(1.27,45.36) v1(1.27,42.82) v1(1.27,40.28) v1(1.27,37.74) v1(1.27,35.2) v1(1.27,32.66) v1(1.27,30.12) v1(1.27,27.58) v1(1.27,25.04) v1(1.27,22.5) v1(1.27,19.96) v1(1.27,17.42) v1(1.27,14.88) v1(1.27,12.34) v1(1.27,9.8) v1(3.17,131.72) v1(5.71,131.72) v1(8.26,131.72) v1(10.79,131.72) v1(10.79,1.27) v1(13.34,131.72) v1(13.34,1.27) v1(15.88,131.72) v1(15.88,1.27) v1(18.41,131.72) v1(18.41,1.27) v1(20.95,131.72) v1(20.95,1.27) v1(23.5,1.27) v1(26.04,1.27) v1(28.57,1.27) v1(31.11,131.72) v1(31.11,1.27) v1(33.66,131.72) v1(33.66,1.27) v1(36.2,131.72) v1(36.2,1.27) v1(38.73,131.72) v1(38.73,1.27) v1(41.27,131.72) v1(41.27,1.27) v1(43.81,131.72) v1(43.81,1.27) v1(46.21,1.12) v1(46.35,131.72) v1(48.9,131.72) v1(48.9,1.27) v1(51.44,131.72) v1(51.44,1.27) v1(53.98,131.72) v1(53.98,1.27) v1(56.52,131.72) v1(56.52,1.27) v1(59.05,131.72) v1(59.05,1.27) v1(61.59,131.72) v1(61.59,1.27) v1(64.14,131.72) v1(64.14,1.27) v1(66.63,1.11) v1(66.67,131.72) v1(69.22,131.72) v1(69.22,1.08) v1(71.75,131.72) v1(71.75,1.08) v1(74.3,131.72) v1(74.3,1.27) v1(76.83,131.72) v1(76.83,1.27) v1(79.38,131.72) v1(79.38,1.27) v1(81.92,131.72) v1(81.92,1.27) v1(84.37,131.72) v1(84.45,1.27) v1(87,131.72) v1(87,1.27) v1(89.53,131.72) v1(89.53,1.27) v1(92.08,131.72) v1(92.08,1.27) v1(94.61,131.72) v1(94.61,1.27) v1(97.16,131.72) v1(97.16,1.27) v1(99.69,131.72) v1(99.69,1.27) v1(102.24,131.84) v1(102.23,1.27) v1(104.78,131.72) v1(104.95,1.45) v1(107.31,131.72) v1(107.31,1.27) v1(109.86,131.72) v1(109.86,1.27) v1(112.39,131.72) v1(114.94,131.72) v1(114.93,1.27) v1(117.47,131.72) v1(117.47,1.27) v1(120.02,131.72) v1(120.02,1.27) v1(122.56,131.72) v1(122.56,1.27) v1(125.09,131.72) v1(125.09,1.27) v1(127.64,131.72) v1(127.64,1.27) v1(130.18,1.27) v1(132.72,1.27) v1(135.25,1.27) v1(137.79,131.72) v1(137.79,1.27) v1(140.34,131.72) v1(140.34,1.27) v1(140.64,68.4) v1(140.67,67.28) v1(141.44,69.67) v1(142.35,69.71) v1(142.8,65.96) v1(142.88,131.72) v1(142.88,1.27) v1(143.27,69.64) v1(145.41,131.72) v1(145.41,1.27) v1(145.65,59) v1(147.96,131.72) v1(147.96,1.27) v1(149.48,80.39) v1(150.39,80.14) v1(150.37,78.94) v1(150.5,131.72) v1(150.5,1.27) v1(153.03,131.72) v1(153.03,1.27) v1(155.57,131.72) v1(155.57,1.27) v1(157.99,62.74) v1(157.99,61.47) v1(157.99,60.2) v1(158.12,131.72) v1(158.12,1.27) v1(159.26,115.44) v1(159.26,114.17) v1(159.26,112.9) v1(159.26,111.63) v1(159.26,62.74) v1(159.26,61.47) v1(159.26,60.2) v1(159.26,58.93) v1(160.53,114.17) v1(160.53,112.9) v1(160.53,111.63) v1(160.53,61.47) v1(160.53,60.2) v1(160.66,131.72) v1(160.66,1.27) v1(160.91,80.7) v1(161.44,82.5) v1(161.8,114.17) v1(161.8,112.9) v1(161.8,62.74) v1(161.8,60.2) v1(161.8,58.93) v1(162.61,82.55) v1(162.71,41.62) v1(163.07,115.44) v1(163.07,112.9) v1(163.07,111.63) v1(163.19,131.72) v1(163.19,1.27) v1(163.99,41.46) v1(164.96,41.43) v1(165.74,131.72) v1(165.74,1.27) v1(165.96,41.43) v1(168.28,131.72) v1(168.28,1.27) v1(170.81,131.72) v1(170.81,1.27) v1(173.35,131.72) v1(173.35,1.27) v1(175.9,131.72) v1(175.9,1.27) v1(178.44,131.72) v1(178.44,1.27) v1(180.97,131.72) v1(180.97,1.27) v1(183.51,131.72) v1(183.51,1.27) v1(184.53,14.54) v1(184.53,12.76) v1(186.06,131.72) v1(186.06,1.27) v1(186.31,14.54) v1(188.13,49.44) v1(188.59,131.72) v1(188.59,1.27) v1(189.39,49.39) v1(190.54,49.39) v1(191.13,131.72) v1(193.68,131.72) v1(194.15,47.5) v1(194.25,46.45) v1(194.28,45.27) v1(198.58,11.84) v1(198.73,113.31) v1(198.73,99.34) v1(198.73,90.45) v1(198.73,80.29) v1(198.73,58.06) v1(198.73,55.52) v1(198.73,52.98) v1(198.73,40.28) v1(198.73,32.66) v1(198.73,30.12) v1(198.73,27.58) v1(198.73,25.04) v1(198.73,22.5) v1(198.68,18.14) v2(89.23,74.7) v2(89.84,73.95) v2(91.66,80.09) v2(93.9,80.83) v2(97.51,74.23) v2(97.77,78.29) v2(97.87,79.31) v2(97.94,72.08) v2(98.04,76.64) v2(98.39,80.06) v2(99.21,76.63)
P5V: length 592.8
  TOP w0.254: J3.11 89.99,121.34 v1(89.75,121.58) 89.49,121.32 J3.9 ; v1(92.65,3.43) 92.39,3.17 91.65,3.17
  TOP w0.279: J2.11 38.87,119.01 v1(38.61,118.75) 38.37,118.98 J2.9
  TOP w0.381: C5.1 90.11,121.94 v1(89.75,121.58) ; v1(123.55,39.38) 123.55,39.27 123.8,39.01 J30.1 ; J58.1 v1(79.2,3.38)
  TOP w0.508: v1(125.4,67.62) 125.4,67.61 124.97,67.18 124.97,66.56 128.92,62.61 128.92,62.22 129.56,61.58 ; 129.56,61.58 129.56,59.61 129.45,59.51 129.45,55.65 128.1,54.31 121.69,54.31 v1(118.31,57.69) ; 129.56,61.58 129.82,61.32 130.58,61.32 131.42,62.15 132.05,62.15 132.74,61.47 133.89,61.47 136.55,58.8 137.39,58.8 139.34,60.76 141.29,60.76 143.18,62.65 143.18,65.27 143.56,65.65 143.56,68.77 144.09,69.3 144.09,69.94 143.18,70.85 R19.1 143.18,75.13 TP33.1 ; v1(38.61,118.75) 38.61,122.54 C3.1 ; v1(7.87,6.1) 7.87,4.05 8.83,3.1 9.89,3.1 11.47,4.67 v1(14.7,4.67) ; v1(123.72,18.02) 125.65,18.02 128.26,15.41 128.26,10.19 126.99,8.91 126.99,3.38 126.97,3.36 v1(126.95,3.36)
  LY3 w0.508: v1(92.65,3.43) 94.74,3.43 95.33,2.85 96.89,2.85 97.98,3.94 98.61,3.94 99.77,2.78 104.24,2.78 104.35,2.9 106.25,2.9 106.36,2.78 113.07,2.78 113.13,2.72 114.34,2.72 115.63,2.72 115.97,3.06 119.3,3.06 119.64,3.39 126.93,3.39 v1(126.95,3.36) ; v1(139.14,34.34) v1(136.2,34.34) ; v1(177.86,8.89) 177.84,8.89 176.74,9.99 v1(176.74,38.62) ; v1(123.72,18.02) 123.72,20.67 123.36,21.03 123.36,21.91 126.58,25.14 128.81,25.14 129.26,25.58 129.26,27.2 125.96,30.5 125.96,31.01 125.26,31.71 125.26,33.06 125.29,33.09 125.29,37.64 v1(123.55,39.38) 123.55,40.28 122.94,40.89 122.94,42.29 122.44,42.79 122.44,43.82 122.25,44.01 122.25,44.86 118.29,48.82 118.29,51.85 118.29,51.85 118.29,52.52 117.73,53.08 117.73,53.47 118.04,54.21 118.06,54.33 118.31,54.58 v1(118.31,57.69)
  LY4 w0.508: v1(79.2,3.38) 79.16,3.34 78.61,3.34 78.57,3.38 74.75,3.38 73.79,2.41 73.15,2.41 73.1,2.47 68.89,2.47 68.71,2.29 63.12,2.29 62.94,2.47 49.73,2.47 49.24,2.96 46.57,2.96 46.08,2.47 26.66,2.47 26.6,2.41 20.81,2.41 19.6,3.62 15.75,3.62 v1(14.7,4.67) ; v1(136.2,34.34) 130.99,34.34 125.95,39.38 v1(123.55,39.38) ; v1(139.14,34.34) 140.01,35.21 144.12,35.21 144.98,34.35 144.98,32.4 148.48,28.9 151.97,28.9 153.47,30.4 175.5,30.4 175.5,30.4 176.44,31.34 176.44,38.31 v1(176.74,38.62) 188.61,38.62 v1(189.15,39.17) ; v1(7.87,6.1) 6.86,7.11 6.86,10.41 2.54,14.73 2.54,63.25 7.34,68.05 J20.8
  BOTTOM w0.254: C705.2 92.52,3.3 v1(92.65,3.43)
  BOTTOM w0.381: Q506.2 177.09,8.09 R758.2 ; R775.1 v1(7.87,6.1) ; C684.2 123.08,38.91 v1(123.55,39.38) ; v1(14.7,4.67) 14.7,4.09 14.97,3.82 R786.1 ; v1(189.15,39.17) R713.2
  BOTTOM w0.508: R641.1 124.46,66.66 125.41,67.6 125.41,67.62 v1(125.4,67.62) ; R758.2 177.05,8.89 v1(177.86,8.89) ; v1(92.65,3.43) 92.01,4.06 92.01,4.7 91.38,5.33 86.68,5.33 84.08,2.74 79.84,2.74 v1(79.2,3.38) ; J20.8 7.47,68.05 9.53,70.1 9.53,89.28 8.76,90.04 8.76,95.76 19.94,106.93 22.99,106.93 25.65,109.6 25.65,112.14 33.78,120.27 37.08,120.27 v1(38.61,118.75) 40.6,120.74 48.69,120.74 50.8,118.63 58.31,118.63 59.18,119.5 62.38,119.5 63.62,120.74 68.63,120.74 68.72,120.66 70.62,120.66 71.75,121.79 71.75,123.27 71.3,123.73 71.3,128.34 72.06,129.1 79.04,129.1 80.91,127.22 81.81,127.22 84.29,124.75 88.03,124.75 89.75,123.03 v1(89.75,121.58)
P5V_CONN: length 2.8
  BOTTOM w0.508: J37.4 191.08,35.08 v1(191.08,36.51) 191.08,37.84 R713.1
P5V_IR: length 4
  BOTTOM w0.508: R508.1 10.16,123.24 C506.2 10.16,123.14 U1.3
P5V_IR_CONN: length 4.2
  TOP w0.508: U21.3 C37.2 188.4,6.97 R66.1
P12V: length 740.3
  TOP w0.178: v1(154.13,62.87) 154.41,62.58 U15.27
  TOP w0.203: U2.9 164.46,114.79 164.19,115.05 164.19,116.31 v2(164.16,116.34)
  TOP w0.254: U2.23 158.91,119.16 159.13,119.38 159.69,119.38 v1(159.71,119.4) 159.71,119.14 159.41,118.84 U2.22 ; U15.37 156.84,56.69 v2(155.99,56.69) ; U15.9 v2(162.98,62.08) ; U15.42 159.64,57.34 160.02,57.72 160.14,57.72 v2(160.14,57.72) ; U2.27 v2(158.04,115.29) ; v2(157.35,109.44) 158.07,109.44 U2.37 ; U15.22 158.14,63.93 v2(158.14,63.93) ; U2.43 161.41,110.42 v2(161.42,110.43) 161.29,110.43 160.91,110.05 U2.42
  TOP w0.381: v1(15.26,15.99) 15.26,15.93 13.4,14.08 J39.1 ; C18.1 180.48,103.24 181.04,102.68 181.04,102.23 v1(181.42,101.85) ; J57.1 68.05,3.38 68.38,3.71 v1(68.38,4.28)
  TOP w0.508: C19.1 187.9,93.35 187.52,93.72 187.52,94.35 187.61,94.43 187.61,94.65 R15.2 189.01,97.74 v1(188.16,97.74) 185.53,97.74 v1(181.42,101.85) ; v1(132.37,4.05) 132.37,4.31 132.78,4.71 132.78,20.63 v1(131.48,21.92) ; J23.2 v1(6.26,59.44) ; R11.2 v1(139.32,102.62) ; v1(136.84,105.41) 132.8,109.45 132.8,114.7 135.32,117.23 135.32,120.04 134.88,120.49 125.99,120.49 118.09,128.38 114.57,128.38 114.25,128.06 113.01,128.06 111.1,126.15 105.41,126.15 103.45,128.11 103.27,128.11 103.26,128.11 102.75,128.11 100.79,126.15 88.64,126.15 87.44,124.95 R1.1 ; v1(172.35,33.02) Q5.2 167.89,33.02 166.32,34.59 165.07,34.59 164.71,34.23 164.71,33.24 Q5.4
  LY3 w0.102: 88.85,19.61 v1(89.56,20.32) v1(89.56,21.59) 89.03,22.12 89.03,27.05 89.28,27.3 90.04,27.3 90.68,27.94 v1(90.83,27.94)
  LY3 w0.508: 60.35,7.5 60.71,7.85 60.71,12.45 61.79,13.53 63.77,13.53 63.88,13.41 66.12,13.41 69.72,17.02 78.49,17.02 80.14,18.67 87.91,18.67 88.85,19.61 ; 60.35,7.5 63.28,7.5 66.49,4.28 v1(68.38,4.28) 69.57,5.48 75.57,5.48 76.06,5.96 78.6,5.96 79.05,6.41 93.74,6.41 93.9,6.25 96.47,6.25 96.63,6.09 100.26,6.09 100.53,5.82 101.39,5.82 102.48,6.9 108.42,6.9 108.93,6.39 108.93,4.75 109.5,4.18 113.14,4.18 113.56,3.76 114.77,3.76 115.2,3.76 115.73,4.29 116.95,4.29 118.93,6.27 125.63,6.27 127.19,4.71 127.21,4.71 128.17,3.75 132.07,3.75 v1(132.37,4.05) ; 60.35,7.5 58.16,7.5 56.64,5.98 47.48,5.98 44.72,3.23 39.82,3.23 39.03,4.01 27.29,4.01 23.94,7.37 19.75,7.37 19.58,7.19 17.39,7.19 16.01,8.56 16.01,15.23 v1(15.26,15.99) ; J36.2 181.01,38.85 180.29,38.85 177.99,41.16 177.14,41.16 v1(176.35,41.95) ; v1(181.42,101.85) 181.42,106.55 179.41,108.56 179.41,110.33 180.4,111.32 180.4,121.53 179.88,122.05 v1(179.88,125.91) ; v1(172.35,33.02) 170.18,30.85 v1(170.18,23.62) 169.06,22.5 169.06,16.44 170.18,15.32 v1(170.18,9.65)
  LY4 w0.508: v1(177.74,62.87) 176.46,62.87 175.42,63.91 173.88,63.91 173.84,63.87 173.21,63.87 173.17,63.91 166.21,63.91 165.72,63.42 165.03,63.42 163.69,62.08 v2(162.98,62.08) ; v1(170.18,9.65) 170.16,9.65 168.89,10.92 161.67,10.92 160.4,9.65 v1(158.12,9.65) 158.08,9.65 156.81,10.92 147.32,10.92 v1(146.05,9.65) ; v1(131.48,21.92) 134.25,24.69 142.61,24.69 143.68,23.62 v1(144.78,23.62) 148.4,23.62 149.47,24.69 156.22,24.69 157.29,23.62 v1(158.12,23.62) 159.75,23.62 160.9,24.77 169.04,24.77 170.18,23.63 v1(170.18,23.62)
  BOTTOM w0.254: J500.15F v1(90.83,27.94)
  BOTTOM w0.381: C527.2 188.16,98.79 v1(188.16,97.74) 186.12,97.74 185.66,97.28 U505.2 ; v1(176.35,41.95) 176.35,41.66 173.85,39.16 R714.1 173.77,38.61 R716.1 172.44,38.08 171.94,37.58 170.92,37.58 170.58,37.92 170.58,39.69 171.32,40.43 171.32,41.34 v1(170.81,41.85) R706.1 ; C706.2 68.1,3.05 68.38,3.32 v1(68.38,4.28) ; C638.1 v1(177.74,62.87) ; DN500.2 v1(179.88,125.91) ; DN501.2 v1(168.19,129.01)
  BOTTOM w0.508: v1(139.32,102.62) 138.01,102.62 136.84,103.78 v1(136.84,105.41) ; v1(176.35,41.95) 176.77,42.37 C672.1 179.11,46.48 179.11,48.6 TP51.1 177.52,50.19 174.4,50.19 173.66,50.93 173.66,52.38 174.74,53.46 177.82,53.46 178.44,54.08 ; J36.2 173.88,34.54 v1(172.35,33.02) ; C665.2 159.89,57.47 160.14,57.72 v2(160.14,57.72) ; v1(179.88,125.91) 179.88,127.33 178.21,129.01 v1(168.19,129.01) ; v2(164.16,116.34) 164.19,116.34 164.76,115.77 C512.2 ; 160.68,86.49 159.7,87.47 155.16,87.47 154.22,86.53 150.13,86.53 148.77,85.17 148.77,84.68 147.74,83.65 147.74,83.04 148.22,82.56 149.74,82.56 DN507.2 ; 160.68,86.49 161.16,86.96 162.95,86.96 163.35,86.57 ; 160.68,86.49 DN506.2 ; v2(161.42,110.43) 161.16,110.17 C519.2 ; 163.35,86.57 DN505.2 ; 163.35,86.57 v1(163.35,86.61) ; v1(177.74,62.87) 177.74,54.78 178.44,54.08 ; DN501.2 166.41,129.01 166.09,128.69 163.54,128.69 163.39,128.54 163.27,128.54 162.89,128.17 DN502.2 160.58,128.17 DN503.2 ; v1(6.26,59.44) 6.26,59.98 8.06,61.79 11.75,61.79 13.08,63.12 13.08,66.8 15.88,69.6 15.88,88.82 18.03,90.98 18.03,91 18.4,91.36 18.41,91.36 19.25,92.2 FB504.2 19.25,94.23 C564.1 ; 178.44,54.08 C664.1 ; J23.2 4.51,54.77 4.51,35.18 6.03,33.66 19.05,33.66 J40.1 J40.2 22.52,28.26 22.48,28.26 19.11,24.89 19.11,19.24 17.5,17.63 16.89,17.63 v1(15.26,15.99) ; J500.16A v1(89.56,20.32) ; C641.2 v1(157.35,71) ; v1(154.13,62.87) 153.41,62.87 151.04,65.23 149.24,65.23 149.16,65.15 149.11,65.15 148.13,64.17 R634.2 ; J500.16B v1(89.56,21.59) ; DN508.2 v1(164.92,73.76) ; v2(162.98,62.08) 163.97,63.07 C639.2
  BOTTOM w0.635: R760.2 157.1,8 158.12,9.02 v1(158.12,9.65) ; v1(170.18,9.65) 170.18,9.02 169.16,8 R759.2 ; R761.2 145.03,8 146.05,9.02 v1(146.05,9.65) ; v1(144.78,23.62) 144.78,22.99 143.76,21.97 R732.2 ; v1(158.12,23.62) 158.12,22.99 157.1,21.97 R731.2 ; R730.2 169.16,21.97 170.18,22.99 v1(170.18,23.62)
  BOTTOM w0.914: v2(157.35,109.44) 157.04,109.12 C520.2 ; v1(160.26,123.06) 159.25,123.06 C505.2 ; v2(155.99,56.69) 155.99,56.64 155.77,56.41 C666.2
P12V_FIL: length 32
  TOP w0.508: C32.1 176.42,33.03 R37.2 ; TP53.1 187.91,40.26 FB8.2 187.32,39.07 C29.2 188.21,37.69 189.26,36.65 189.26,35.55 188.52,34.81 R40.1 187.03,34.52 R39.1 183.03,34.52 J36.1 181.18,36.38 178.55,36.38 176.47,34.29 R37.2 ; R37.2 176.42,34.4 176.09,34.73 175.5,35.32 Q5.3
P12V_IN: length 26.8
  TOP w0.508: 188.65,45.08 192,41.72 192,38.22 192.66,37.57 192.66,30.5 J37.6 ; C28.2 185.42,39.04 FB8.1 185.09,40.52 187.85,43.29 187.85,44.91
VDD1_INDEX_SENSE: length 14.4
  TOP w0.178: v1(122.48,5.13) 122.38,5.13 122.28,5.03 122.28,4.3 121.9,3.92 J62.1
  BOTTOM w0.178: C703.2 114.73,3.17 R780.1 114.99,3.19 116.04,2.14 121.47,2.14 122.28,2.95 122.28,5.03 122.38,5.13 v1(122.48,5.13)
VDD2_INDEX_SENSE: length 5.7
  TOP w0.178: J60.1 v1(102.21,5.05)
  BOTTOM w0.178: v1(102.21,5.05) 102.21,4.77 R781.1 103.3,3.17 C704.2
VDD_TILT: length 6.2
  TOP w0.178: U3.8 183.13,112.32 183.13,111.51 183.77,110.87 v1(183.83,110.87)
  BOTTOM w0.178: v1(183.83,110.87) 183.83,111.76 183.16,112.43 R512.1 183.02,112.32 C508.2
3D_TOGGLE: length 253.1
  TOP w0.178: U11.E26 v2(84.66,89.2)
  LY3 w0.171: v1(5.97,17.02) 6.07,17.12 8.32,17.12 9.01,17.81 10.5,17.81 11.1,18.41 11.1,19.26 10.68,19.68 10.68,20.58 10.2,21.06 10.2,23.36 10.67,23.84 10.67,75.6 11.67,76.6 11.67,79.07 12.76,80.17 v1(12.76,89)
  LY4 w0.171: v1(5.97,17.02) 8.28,14.71 12.15,14.71 15.57,11.3 17.3,11.3 17.85,11.84 18.34,11.84 18.89,11.3 33.56,11.3 36.71,8.15 40.42,8.15 40.43,8.16 40.92,8.16 40.93,8.15 50.19,8.15 52.73,10.7 73.69,10.7 v1(73.98,10.41) ; v2(84.66,89.2) 84.66,89.79 82.99,91.46 82.99,91.71 82.44,92.27 82.18,92.27 81.78,92.67 78.97,92.67 78.35,93.28 78.35,93.29 77.68,93.96 73.25,93.96 73.11,93.81 71.21,93.81 70.45,93.06 69.8,93.06 68.28,94.58 66.85,94.58 66.43,95 63.43,95 63.33,94.89 61.19,94.89 60.94,95.15 58.78,95.15 58.41,95.52 51.77,95.52 48.79,92.53 47,92.53 46.09,93.45 45.33,93.45 42.18,96.6 42.18,96.62 40.58,98.22 35.3,98.22 34.75,98.77 31.65,98.77 30.31,100.1 29.43,100.1 28.87,100.66 26.28,100.66 25.58,101.36 25.45,101.36 22.73,101.36 21.53,102.57 13.75,102.57 13.16,102.57 11.7,101.11 11.7,100.76 11.7,100.46 11.7,100.17 11.7,90.06 v1(12.76,89)
  BOTTOM w0.178: U522.2 74.17,10.22 v1(73.98,10.41) ; U519.8 5.25,15.45 5.97,16.17 v1(5.97,17.02)
A1P8V: length 195.4
  TOP w0.508: v1(87.26,128.29) 87.26,127.91 85.28,125.93 85.28,122.75 v1(85.88,122.15) 83.46,119.74 83.46,118.55 83.46,117.82 83.26,117.63 83.26,116.09 84.2,115.15 84.2,111.63 83.44,110.87 83.44,108.58 84.06,107.96 88.43,107.96 89.28,107.12 89.28,105.66 88.79,105.17 88.79,104.7 88.52,104.43 88.05,104.43 87.64,104.03 87.64,103.43 84.71,100.5 84.71,99.06 80.83,95.18 v1(80.83,94.83)
  BOTTOM w0.483: R620.1 v1(151.76,69.72)
  BOTTOM w0.508: v1(80.83,94.83) 80.83,95.12 80.83,95.12 R527.1 ; v1(151.76,69.72) 151.76,70.17 149.67,72.26 146.88,72.26 146.24,72.9 146.24,83.12 147.73,84.61 147.73,84.67 148.09,85.03 148.09,89.09 147.12,90.05 147.11,90.06 147.11,90 147.04,90.07 144.48,90.07 141.41,93.13 141.41,95.04 138.24,98.21 138.24,98.62 136.27,100.59 136.27,101.25 133.09,104.44 133.09,106.58 134.43,107.93 135.08,107.93 135.52,108.37 135.52,111.47 136.23,112.18 136.23,113.44 136.59,113.79 136.59,116.39 136.32,116.65 136.32,119.62 140.02,123.32 144.08,123.32 147.79,127.02 147.79,127.74 146.05,129.48 140.08,129.48 135.42,124.82 130.16,124.82 124.02,130.96 122.98,130.96 102.35,130.96 102.23,131.08 100.13,131.08 100.01,130.96 87.9,130.96 87.26,130.33 v1(87.26,128.29)
